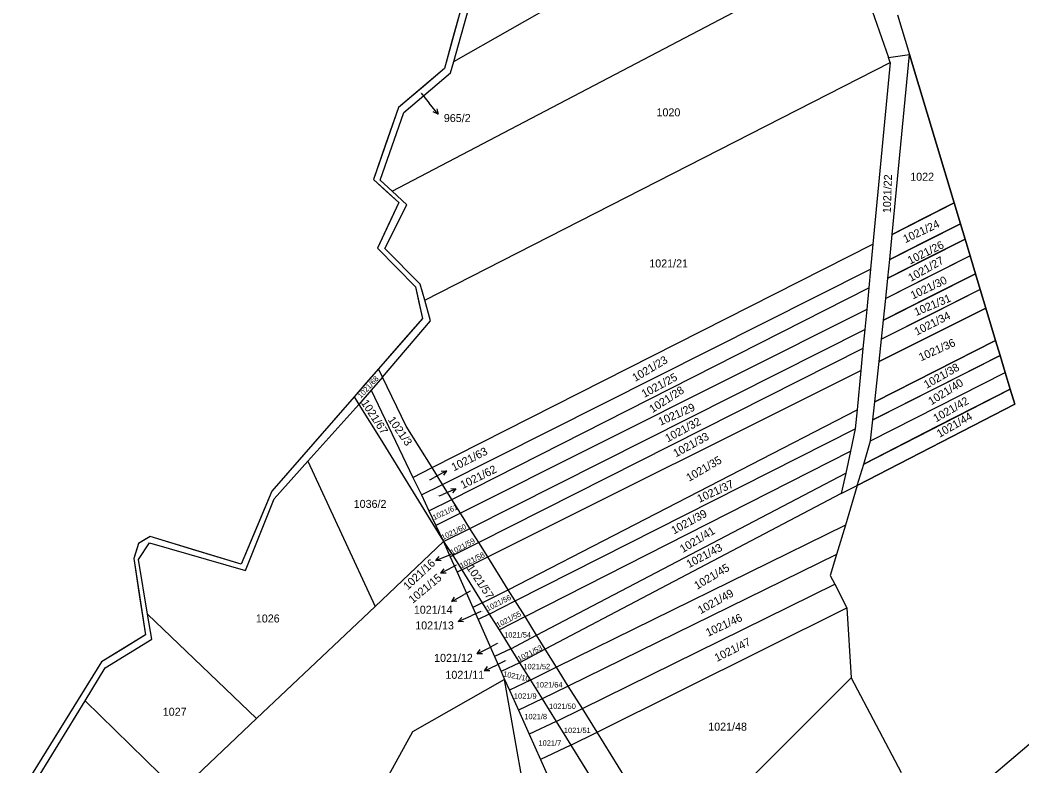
# Model space of a CAD drawing. Extents: x -593358 to -590116, y -1072518 to -1068420.
# Drawn here: x -592072.7 to -591859.9, y -1072242.9 to -1072084.5 of the extents above; entities that cross this region are included whole.
import ezdxf

# ---------------------------------------------------------------- set-up
doc = ezdxf.new("R2010")
doc.units = 0
for name, color, linetype in [('katastrální hranice', 7, 'Continuous'), ('lesy', 7, 'Continuous'), ('Parcela KN', 7, 'Continuous'), ('Parcela ZE', 7, 'Continuous'), ('Parcelní číslo', 7, 'Continuous'), ('vnější obvod_šetřený', 7, 'Continuous'), ('Vrstva 16', 7, 'Continuous')]:
    doc.layers.add(name, color=color, linetype=linetype)

msp = doc.modelspace()

# ---------------------------------------------------------------- linework, layer by layer
at = {"layer": 'katastrální hranice'}
for p, q in [((-591979.08, -1072082.21), (-591982.55, -1072094.78)), ((-591982.55, -1072094.78), (-591992.32, -1072103.06)), ((-591992.32, -1072103.06), (-591997.61, -1072118.38)), ((-591997.61, -1072118.38), (-591992.21, -1072123.21)), ((-591992.21, -1072123.21), (-591996.78, -1072132.9)), ((-591996.78, -1072132.9), (-591988.71, -1072141.11)), ((-591988.71, -1072141.11), (-591987.21, -1072147.83)), ((-591987.21, -1072147.83), (-591996.54, -1072158.54)), ((-591996.54, -1072158.54), (-592001.74, -1072164.5)), ((-592001.74, -1072164.5), (-592019.22, -1072184.56)), ((-592019.22, -1072184.56), (-592025.7, -1072200.04)), ((-592047.5, -1072195.64), (-592048.53, -1072198.82)), ((-592045, -1072194.14), (-592047.5, -1072195.64)), ((-592025.7, -1072200.04), (-592045, -1072194.14)), ((-592048.53, -1072198.82), (-592046.03, -1072215.04)), ((-592046.03, -1072215.04), (-592055.36, -1072220.77)), ((-592055.36, -1072220.77), (-592072.66, -1072248.65))]:
    msp.add_line(p, q, dxfattribs=at)
at = {"layer": 'lesy'}
for points in [[(-591894.9, -1072183.35), (-591861.47, -1072166.07), (-591862.43, -1072162.87), (-591863.51, -1072159.3), (-591864.59, -1072155.73), (-591865.54, -1072152.56), (-591867.62, -1072145.66), (-591868.81, -1072141.69), (-591869.81, -1072138.36), (-591870.95, -1072134.57), (-591872.03, -1072131), (-591873, -1072127.77), (-591874.34, -1072123.33), (-591883.84, -1072091.8)], [(-591874.34, -1072123.33), (-591880.91, -1072126.66), (-591887.48, -1072129.99)], [(-591873, -1072127.77), (-591880.495, -1072131.54), (-591887.99, -1072135.31)], [(-591872.03, -1072131), (-591880.22, -1072135.155), (-591888.41, -1072139.31)], [(-591870.95, -1072134.57), (-591879.91, -1072139.09), (-591888.87, -1072143.61)], [(-591869.81, -1072138.36), (-591879.585, -1072143.285), (-591889.36, -1072148.21)], [(-591868.81, -1072141.69), (-591879.3, -1072146.985), (-591889.79, -1072152.28)], [(-591867.62, -1072145.66), (-591878.955, -1072151.32), (-591890.29, -1072156.98)], [(-591865.54, -1072152.56), (-591878.37, -1072159.06), (-591891.2, -1072165.56)], [(-591864.59, -1072155.73), (-591878.1, -1072162.57), (-591891.61, -1072169.41)], [(-591862.43, -1072162.87), (-591877.99, -1072170.82), (-591893.55, -1072178.77)]]:
    msp.add_lwpolyline(points, dxfattribs=at)
at = {"layer": 'Parcela KN'}
for p, q in [((-591896.24, -1072069.74), (-591888.25, -1072092.44)), ((-591980.58, -1072093.29), (-591977.46, -1072082.16)), ((-591886.38, -1072083.38), (-591883.84, -1072091.8)), ((-591888.25, -1072092.44), (-591883.84, -1072091.8)), ((-591883.84, -1072091.8), (-591874.34, -1072123.33)), ((-591981.26, -1072095.73), (-591980.58, -1072093.29)), ((-591991.15, -1072104.09), (-591981.26, -1072095.73)), ((-591996.21, -1072118.49), (-591991.15, -1072104.09)), ((-591993.67, -1072120.83), (-591996.21, -1072118.49)), ((-591990.52, -1072123.74), (-591993.67, -1072120.83)), ((-591995.22, -1072132.98), (-591990.52, -1072123.74)), ((-591874.34, -1072123.33), (-591873, -1072127.77)), ((-591873, -1072127.77), (-591872.03, -1072131)), ((-591872.03, -1072131), (-591870.95, -1072134.57)), ((-591987.68, -1072140.56), (-591995.22, -1072132.98)), ((-591870.95, -1072134.57), (-591869.81, -1072138.36)), ((-591869.81, -1072138.36), (-591868.81, -1072141.69)), ((-591986.73, -1072144), (-591987.68, -1072140.56)), ((-591868.81, -1072141.69), (-591867.62, -1072145.66)), ((-591985.53, -1072148.33), (-591986.73, -1072144)), ((-591867.62, -1072145.66), (-591865.54, -1072152.56)), ((-591995.69, -1072160.3), (-591985.53, -1072148.33)), ((-591865.54, -1072152.56), (-591864.59, -1072155.73)), ((-591864.59, -1072155.73), (-591863.51, -1072159.3)), ((-591995.69, -1072160.3), (-591996.54, -1072158.54)), ((-591863.51, -1072159.3), (-591862.43, -1072162.87)), ((-591990.69, -1072170.71), (-591995.69, -1072160.3)), ((-591862.43, -1072162.87), (-591861.47, -1072166.07)), ((-592011.53, -1072178.15), (-592000.75, -1072166.09)), ((-592001.74, -1072164.5), (-592000.75, -1072166.09)), ((-592000.75, -1072166.09), (-591996.21, -1072173.37)), ((-591861.47, -1072166.07), (-591894.9, -1072183.35)), ((-591985.19, -1072179.53), (-591990.69, -1072170.71)), ((-591996.21, -1072173.37), (-591982.74, -1072195.23)), ((-592018.68, -1072186.15), (-592011.53, -1072178.15)), ((-591982.98, -1072183.08), (-591985.19, -1072179.53)), ((-591981, -1072186.26), (-591982.98, -1072183.08)), ((-591894.9, -1072183.35), (-591897.42, -1072191.71)), ((-592024.76, -1072201.4), (-592018.68, -1072186.15)), ((-591979.18, -1072189.17), (-591981, -1072186.26)), ((-591977.15, -1072192.42), (-591979.18, -1072189.17)), ((-591897.42, -1072191.71), (-591899.31, -1072197.99)), ((-591975.28, -1072195.41), (-591977.15, -1072192.42)), ((-592047.51, -1072199.03), (-592045.17, -1072195.52)), ((-592045.17, -1072195.52), (-592024.76, -1072201.4)), ((-591982.74, -1072195.23), (-591981.31, -1072198.44)), ((-591982.74, -1072195.23), (-591980.77, -1072198.19)), ((-591973.37, -1072198.48), (-591975.28, -1072195.41)), ((-591980.77, -1072198.19), (-591981.31, -1072198.44)), ((-591980.77, -1072198.19), (-591978.88, -1072201.23)), ((-591899.31, -1072197.99), (-591900.65, -1072202.43)), ((-592045.58, -1072210.63), (-592047.51, -1072199.03)), ((-591981.31, -1072198.44), (-591979.87, -1072201.7)), ((-591969.02, -1072205.45), (-591973.37, -1072198.48)), ((-591978.88, -1072201.23), (-591979.87, -1072201.7)), ((-591979.87, -1072201.7), (-591976.54, -1072209.22)), ((-591978.88, -1072201.23), (-591974.52, -1072208.26)), ((-591900.65, -1072202.43), (-591899.7, -1072204.29)), ((-591899.7, -1072204.29), (-591897.13, -1072209.29)), ((-591967.53, -1072207.84), (-591969.02, -1072205.45)), ((-591974.52, -1072208.26), (-591976.54, -1072209.22)), ((-591974.52, -1072208.26), (-591973.04, -1072210.63)), ((-591965.45, -1072211.17), (-591967.53, -1072207.84)), ((-592044.7, -1072215.96), (-592045.58, -1072210.63)), ((-591976.54, -1072209.22), (-591975.42, -1072211.76)), ((-591973.04, -1072210.63), (-591975.42, -1072211.76)), ((-591973.04, -1072210.63), (-591970.96, -1072213.97)), ((-591897.13, -1072209.29), (-591896.2, -1072224.13)), ((-591975.42, -1072211.76), (-591971.94, -1072219.64)), ((-591962.98, -1072215.13), (-591965.45, -1072211.17)), ((-591970.96, -1072213.97), (-591968.47, -1072217.99)), ((-591961.14, -1072218.08), (-591962.98, -1072215.13)), ((-592054.56, -1072222.06), (-592044.7, -1072215.96)), ((-591968.47, -1072217.99), (-591971.94, -1072219.64)), ((-591968.47, -1072217.99), (-591966.62, -1072220.96)), ((-591958.75, -1072221.91), (-591961.14, -1072218.08)), ((-591971.94, -1072219.64), (-591970.53, -1072222.82)), ((-591966.62, -1072220.96), (-591970.53, -1072222.82)), ((-591966.62, -1072220.96), (-591964.32, -1072224.65)), ((-592058.85, -1072229.04), (-592054.56, -1072222.06)), ((-591970.53, -1072222.82), (-591969.8, -1072224.48)), ((-591956.26, -1072225.9), (-591958.75, -1072221.91)), ((-591969.8, -1072224.48), (-591989.37, -1072235.64)), ((-591955.53, -1072305.6), (-591969.8, -1072224.48)), ((-591969.8, -1072224.48), (-591968.77, -1072226.76)), ((-591964.32, -1072224.65), (-591968.77, -1072226.76)), ((-591964.32, -1072224.65), (-591961.84, -1072228.64)), ((-591933.86, -1072261.82), (-591896.2, -1072224.13)), ((-591896.2, -1072224.13), (-591885.59, -1072244.24)), ((-591968.77, -1072226.76), (-591966.85, -1072231.03)), ((-591953.28, -1072230.67), (-591956.26, -1072225.9)), ((-592072.08, -1072250.65), (-592058.85, -1072229.04)), ((-591961.84, -1072228.64), (-591966.85, -1072231.03)), ((-591961.84, -1072228.64), (-591958.86, -1072233.42)), ((-591966.85, -1072231.03), (-591964.56, -1072236.12)), ((-591950.15, -1072235.69), (-591953.28, -1072230.67)), ((-591958.86, -1072233.42), (-591964.56, -1072236.12)), ((-591958.86, -1072233.42), (-591955.72, -1072238.46)), ((-591867.4, -1072245.92), (-591851.52, -1072232.33)), ((-591989.37, -1072235.64), (-592021.41, -1072294.03)), ((-591964.56, -1072236.12), (-591962.14, -1072241.51)), ((-591933.86, -1072261.82), (-591950.15, -1072235.69)), ((-591955.72, -1072238.46), (-591962.14, -1072241.51)), ((-591955.72, -1072238.46), (-591938.81, -1072265.63)), ((-591962.14, -1072241.51), (-591956.04, -1072255.12))]:
    msp.add_line(p, q, dxfattribs=at)
at = {"layer": 'Parcela ZE'}
for p, q in [((-591980.58, -1072093.29), (-591904.82, -1072050.13)), ((-591993.67, -1072120.83), (-591896.24, -1072069.74)), ((-591887.48, -1072129.99), (-591883.84, -1072091.8)), ((-591986.73, -1072144), (-591887.89, -1072093.51)), ((-591887.89, -1072093.51), (-591891.59, -1072132.07)), ((-591887.89, -1072093.51), (-591888.25, -1072092.44)), ((-591887.48, -1072129.99), (-591874.34, -1072123.33)), ((-591887.99, -1072135.31), (-591873, -1072127.77)), ((-591887.99, -1072135.31), (-591887.48, -1072129.99)), ((-591985.19, -1072179.53), (-591891.59, -1072132.07)), ((-591891.59, -1072132.07), (-591892.1, -1072137.38)), ((-591888.41, -1072139.31), (-591872.03, -1072131)), ((-591870.95, -1072134.57), (-591888.87, -1072143.61)), ((-591888.41, -1072139.31), (-591887.99, -1072135.31)), ((-591982.98, -1072183.08), (-591892.1, -1072137.38)), ((-591892.1, -1072137.38), (-591892.48, -1072141.37)), ((-591889.36, -1072148.21), (-591869.81, -1072138.36)), ((-591888.87, -1072143.61), (-591888.41, -1072139.31)), ((-591981, -1072186.26), (-591892.48, -1072141.37)), ((-591892.48, -1072141.37), (-591892.91, -1072145.96)), ((-591868.81, -1072141.69), (-591889.79, -1072152.28)), ((-591889.36, -1072148.21), (-591888.87, -1072143.61)), ((-591892.91, -1072145.96), (-591979.18, -1072189.17)), ((-591892.91, -1072145.96), (-591893.33, -1072150.21)), ((-591890.29, -1072156.98), (-591867.62, -1072145.66)), ((-591889.79, -1072152.28), (-591889.36, -1072148.21)), ((-591977.15, -1072192.42), (-591893.33, -1072150.21)), ((-591893.33, -1072150.21), (-591893.72, -1072154.26)), ((-591891.2, -1072165.56), (-591865.54, -1072152.56)), ((-591890.29, -1072156.98), (-591889.79, -1072152.28)), ((-591893.72, -1072154.26), (-591975.28, -1072195.41)), ((-591893.72, -1072154.26), (-591894.16, -1072158.92)), ((-591891.61, -1072169.41), (-591864.59, -1072155.73)), ((-591891.2, -1072165.56), (-591890.29, -1072156.98)), ((-591973.37, -1072198.48), (-591894.16, -1072158.92)), ((-591894.16, -1072158.92), (-591894.95, -1072167.28)), ((-591892.1, -1072173.85), (-591863.51, -1072159.3)), ((-591995.69, -1072160.3), (-591998.12, -1072163.08)), ((-591998.12, -1072163.08), (-592000.75, -1072166.09)), ((-591998.12, -1072163.08), (-591989.25, -1072181.59)), ((-591893.55, -1072178.77), (-591862.43, -1072162.87)), ((-591891.61, -1072169.41), (-591891.2, -1072165.56)), ((-591969.02, -1072205.45), (-591894.95, -1072167.28)), ((-591894.95, -1072167.28), (-591895.37, -1072171.31)), ((-591892.1, -1072173.85), (-591891.61, -1072169.41)), ((-591967.53, -1072207.84), (-591895.37, -1072171.31)), ((-591895.37, -1072171.31), (-591896.38, -1072176.03)), ((-591893.55, -1072178.77), (-591892.1, -1072173.85)), ((-591965.45, -1072211.17), (-591896.38, -1072176.03)), ((-591896.38, -1072176.03), (-591897.37, -1072180.72)), ((-592011.53, -1072178.15), (-591997.26, -1072208.98)), ((-591894.9, -1072183.35), (-591893.55, -1072178.77)), ((-591989.25, -1072181.59), (-591985.19, -1072179.53)), ((-591962.98, -1072215.13), (-591897.37, -1072180.72)), ((-591897.37, -1072180.72), (-591898.3, -1072184.99)), ((-591989.25, -1072181.59), (-591987.46, -1072185.33)), ((-591987.46, -1072185.33), (-591982.98, -1072183.08)), ((-591987.46, -1072185.33), (-591985.84, -1072188.71)), ((-591898.3, -1072184.99), (-591961.14, -1072218.08)), ((-591898.3, -1072184.99), (-591894.9, -1072183.35)), ((-591985.84, -1072188.71), (-591981, -1072186.26)), ((-591985.84, -1072188.71), (-591984.36, -1072191.78)), ((-591979.18, -1072189.17), (-591984.36, -1072191.78)), ((-591984.36, -1072191.78), (-591982.74, -1072195.23)), ((-591897.42, -1072191.71), (-591958.75, -1072221.91)), ((-591982.74, -1072195.23), (-591977.15, -1072192.42)), ((-591982.74, -1072195.23), (-591997.26, -1072208.98)), ((-591975.28, -1072195.41), (-591980.77, -1072198.19)), ((-591899.31, -1072197.99), (-591956.26, -1072225.9)), ((-591978.88, -1072201.23), (-591973.37, -1072198.48)), ((-591953.28, -1072230.67), (-591899.7, -1072204.29)), ((-591974.52, -1072208.26), (-591969.02, -1072205.45)), ((-591973.04, -1072210.63), (-591967.53, -1072207.84)), ((-592045.58, -1072210.63), (-592022.45, -1072232.83)), ((-591997.26, -1072208.98), (-592022.45, -1072232.83)), ((-591950.15, -1072235.69), (-591897.13, -1072209.29)), ((-591970.96, -1072213.97), (-591965.45, -1072211.17)), ((-591968.47, -1072217.99), (-591962.98, -1072215.13)), ((-591961.14, -1072218.08), (-591966.62, -1072220.96)), ((-591958.75, -1072221.91), (-591964.32, -1072224.65)), ((-591956.26, -1072225.9), (-591961.84, -1072228.64)), ((-592058.85, -1072229.04), (-592038.94, -1072248.45)), ((-591958.86, -1072233.42), (-591953.28, -1072230.67)), ((-592022.45, -1072232.83), (-592038.94, -1072248.45)), ((-591955.72, -1072238.46), (-591950.15, -1072235.69))]:
    msp.add_line(p, q, dxfattribs=at)
at = {"layer": 'vnější obvod_šetřený'}
for p, q in [((-591979.08, -1072082.21), (-591980.815, -1072088.495)), ((-591980.815, -1072088.495), (-591982.55, -1072094.78)), ((-591982.55, -1072094.78), (-591987.435, -1072098.92)), ((-591987.435, -1072098.92), (-591992.32, -1072103.06)), ((-591992.32, -1072103.06), (-591994.965, -1072110.72)), ((-591994.965, -1072110.72), (-591997.61, -1072118.38)), ((-591997.61, -1072118.38), (-591994.91, -1072120.795)), ((-591994.91, -1072120.795), (-591992.21, -1072123.21)), ((-591992.21, -1072123.21), (-591994.495, -1072128.055)), ((-591994.495, -1072128.055), (-591996.78, -1072132.9)), ((-591996.78, -1072132.9), (-591992.745, -1072137.005)), ((-591992.745, -1072137.005), (-591988.71, -1072141.11)), ((-591988.71, -1072141.11), (-591987.96, -1072144.47)), ((-591987.96, -1072144.47), (-591987.21, -1072147.83)), ((-591987.21, -1072147.83), (-591991.875, -1072153.185)), ((-591991.875, -1072153.185), (-591996.54, -1072158.54)), ((-591996.54, -1072158.54), (-591999.14, -1072161.52)), ((-591999.14, -1072161.52), (-592001.74, -1072164.5)), ((-592001.74, -1072164.5), (-592010.48, -1072174.53)), ((-592010.48, -1072174.53), (-592019.22, -1072184.56)), ((-592019.22, -1072184.56), (-592022.46, -1072192.3)), ((-592022.46, -1072192.3), (-592025.7, -1072200.04)), ((-592047.5, -1072195.64), (-592048.015, -1072197.23)), ((-592046.25, -1072194.89), (-592047.5, -1072195.64)), ((-592045, -1072194.14), (-592046.25, -1072194.89)), ((-592035.35, -1072197.09), (-592045, -1072194.14)), ((-592048.015, -1072197.23), (-592048.53, -1072198.82)), ((-592025.7, -1072200.04), (-592035.35, -1072197.09)), ((-592048.53, -1072198.82), (-592047.28, -1072206.93)), ((-592047.28, -1072206.93), (-592046.03, -1072215.04)), ((-592046.03, -1072215.04), (-592050.695, -1072217.905)), ((-592050.695, -1072217.905), (-592055.36, -1072220.77)), ((-592055.36, -1072220.77), (-592064.01, -1072234.71)), ((-592064.01, -1072234.71), (-592072.66, -1072248.65))]:
    msp.add_line(p, q, dxfattribs=at)
at = {"layer": 'Vrstva 16'}
for p, q in [((-591987.49, -1072100.01), (-591985.8, -1072102.11)), ((-591983.92, -1072104.448), (-591985.8, -1072102.11)), ((-591982.112, -1072180.211), (-591984.75, -1072181.64)), ((-591985.69, -1072182.15), (-591984.75, -1072181.64)), ((-591983.7, -1072185.55), (-591982.88, -1072185.21)), ((-591980.116, -1072184.043), (-591982.88, -1072185.21)), ((-591984.399, -1072199.22), (-591981.62, -1072198.09)), ((-591981.25, -1072197.94), (-591981.62, -1072198.09)), ((-591980.04, -1072200.24), (-591980.64, -1072200.55)), ((-591983.312, -1072201.915), (-591980.64, -1072200.55)), ((-591981.018, -1072207.965), (-591978.4, -1072206.5)), ((-591977.09, -1072205.77), (-591978.4, -1072206.5)), ((-591974.8, -1072210.09), (-591976.86, -1072210.98)), ((-591979.611, -1072212.176), (-591976.86, -1072210.98)), ((-591971.33, -1072216.89), (-591972.95, -1072217.71)), ((-591975.626, -1072219.067), (-591972.95, -1072217.71)), ((-591974.065, -1072222.667), (-591971.36, -1072221.37)), ((-591969.69, -1072220.57), (-591971.36, -1072221.37))]:
    msp.add_line(p, q, dxfattribs=at)
for points in [[(-591984.157, -1072103.355), (-591983.92, -1072104.448), (-591984.936, -1072103.982)], [(-591983.23, -1072180.248), (-591982.112, -1072180.211), (-591982.753, -1072181.127)], [(-591981.232, -1072183.971), (-591980.116, -1072184.043), (-591980.843, -1072184.892)], [(-591983.284, -1072199.307), (-591984.399, -1072199.22), (-591983.661, -1072198.38)], [(-591982.194, -1072201.905), (-591983.312, -1072201.915), (-591982.649, -1072201.014)], [(-591979.901, -1072207.913), (-591981.018, -1072207.965), (-591980.389, -1072207.04)], [(-591978.495, -1072212.236), (-591979.611, -1072212.176), (-591978.893, -1072211.319)], [(-591974.508, -1072219.06), (-591975.626, -1072219.067), (-591974.96, -1072218.168)], [(-591972.947, -1072222.686), (-591974.065, -1072222.667), (-591973.38, -1072221.784)]]:
    msp.add_lwpolyline(points, dxfattribs=at)

# ---------------------------------------------------------------- texts
at = {"layer": 'Parcelní číslo'}
for s, height, p in [('965/2', 0.1, (-591987.699, -1072100.01)), ('1020', 1.7, (-591937.533, -1072104.94)), ('1022', 1.7, (-591883.669, -1072118.61)), ('1021/21', 1.7, (-591939.062, -1072137.02)), ('1021/63', 0.1, (-591985.943, -1072182.15)), ('1021/62', 0.1, (-591984.002, -1072185.55)), ('1036/2', 1.7, (-592001.822, -1072188.08)), ('1021/15', 0.1, (-591980.27, -1072200.24)), ('1021/14', 0.1, (-591977.318, -1072205.77)), ('1026', 1.7, (-592022.596, -1072212.41)), ('1021/13', 0.1, (-591975.033, -1072210.09)), ('1021/54', 1.14, (-591969.869, -1072215.6)), ('1021/12', 0.1, (-591971.562, -1072216.89)), ('1021/11', 0.1, (-591969.897, -1072220.57)), ('1021/52', 1.14, (-591965.798, -1072222.33)), ('1021/64', 1.14, (-591963.177, -1072226.21)), ('1021/9', 1.14, (-591967.805, -1072228.59)), ('1021/50', 1.14, (-591960.347, -1072230.76)), ('1027', 1.7, (-592042.356, -1072232.21)), ('1021/8', 1.14, (-591965.589, -1072232.95)), ('1021/48', 1.7, (-591926.546, -1072235.38)), ('1021/51', 1.14, (-591957.195, -1072235.88)), ('1021/7', 1.14, (-591962.578, -1072238.58))]:
    msp.add_text(s, height=height, dxfattribs=at).set_placement(p)
for s, height, rotation, p in [('1021/22', 1.7, 88.12091, (-591887.803, -1072125.511)), ('1021/24', 1.7, 25.26744, (-591884.689, -1072131.871)), ('1021/26', 1.7, 26.18417, (-591883.71, -1072136.413)), ('1021/27', 1.7, 29.56462, (-591883.516, -1072140.107)), ('1021/30', 1.7, 25.32473, (-591883.104, -1072143.822)), ('1021/31', 1.7, 22.91831, (-591882.403, -1072147.36)), ('1021/34', 1.7, 26.81443, (-591882.27, -1072151.511)), ('1021/36', 1.7, 24.23611, (-591881.394, -1072156.966)), ('1021/23', 1.7, 30.71054, (-591942.053, -1072161.335)), ('1021/38', 1.7, 29.73651, (-591880.184, -1072162.804)), ('1021/25', 1.7, 28.41871, (-591940.144, -1072164.744)), ('1021/68', 1.14, 47.38361, (-592000.273, -1072164.901)), ('1021/40', 1.7, 32.02834, (-591879.187, -1072166.32)), ('1021/28', 1.7, 32.83048, (-591938.401, -1072167.977)), ('1021/67', 1.7, 303.09467, (-592000.33, -1072165.762)), ('1021/29', 1.7, 23.89234, (-591936.692, -1072170.637)), ('1021/42', 1.7, 29.79381, (-591878.183, -1072169.941)), ('1021/44', 1.7, 29.73651, (-591877.441, -1072173.211)), ('1021/3', 1.7, 304.92814, (-591994.649, -1072169.387)), ('1021/32', 1.7, 28.5333, (-591935.145, -1072174.181)), ('1021/33', 1.7, 28.76248, (-591933.419, -1072177.382)), ('1021/35', 1.7, 30.25217, (-591930.608, -1072182.552)), ('1021/37', 1.7, 24.57989, (-591928.437, -1072187.023)), ('1021/61', 1.14, 25.15285, (-591984.728, -1072190.702)), ('1021/39', 1.7, 28.70519, (-591933.834, -1072193.737)), ('1021/60', 1.14, 25.7831, (-591982.902, -1072194.928)), ('1021/41', 1.7, 31.28349, (-591931.936, -1072197.679)), ('1021/59', 1.14, 28.476, (-591980.933, -1072198.113)), ('1021/43', 1.7, 28.01764, (-591930.639, -1072200.891)), ('1021/16', 0.1, 318.39265, (-591981.44, -1072197.789)), ('1021/58', 1.14, 26.24147, (-591978.976, -1072200.93)), ('1021/57', 1.7, 303.78222, (-591977.938, -1072200.8)), ('1021/45', 1.7, 30.88243, (-591928.909, -1072205.468)), ('1021/56', 1.14, 26.92902, (-591973.329, -1072210.035)), ('1021/49', 1.7, 28.99166, (-591928.168, -1072210.683)), ('1021/55', 1.14, 27.50198, (-591971.184, -1072213.565)), ('1021/46', 1.7, 25.03826, (-591926.58, -1072215.454)), ('1021/53', 1.14, 27.21549, (-591966.694, -1072220.734)), ('1021/47', 1.7, 26.75713, (-591924.689, -1072220.8)), ('1021/10', 1.14, 348.70211, (-591970.171, -1072223.838))]:
    msp.add_text(s, height=height, rotation=rotation, dxfattribs=at).set_placement(p)
at = {"layer": 'Vrstva 16'}
for s, p in [('965/2', (-591982.683, -1072106.15)), ('1021/14', (-591989.054, -1072210.55)), ('1021/13', (-591988.758, -1072213.88)), ('1021/12', (-591984.751, -1072220.77)), ('1021/11', (-591982.348, -1072224.37))]:
    msp.add_text(s, height=1.7, dxfattribs=at).set_placement(p)
for s, rotation, p in [('1021/63', 26.81443, (-591980.56, -1072180.323)), ('1021/62', 26.35606, (-591978.658, -1072184.086)), ('1021/16', 42.97183, (-591990.356, -1072205.609)), ('1021/15', 39.82057, (-591989.288, -1072208.462))]:
    msp.add_text(s, height=1.7, rotation=rotation, dxfattribs=at).set_placement(p)

doc.saveas('drawing.dxf')
